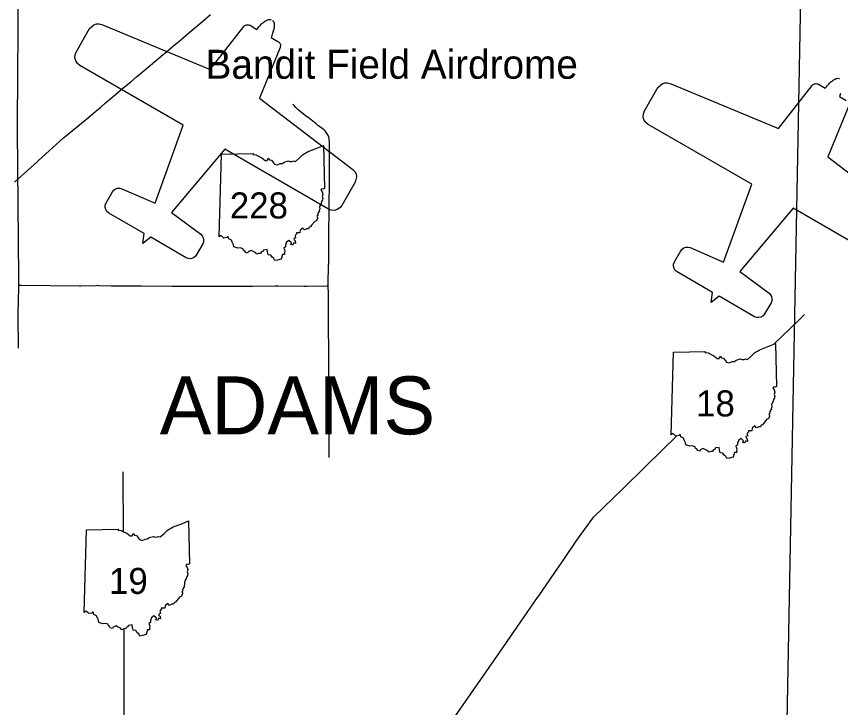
# Model space of a CAD drawing. Extents: x -232 to 448, y 619 to 1059.
# Drawn here: x 309.46 to 338.66, y 749.86 to 774.33 of the extents above; entities that cross this region are included whole.
import ezdxf

# ---------------------------------------------------------------- set-up
doc = ezdxf.new("R2010")
doc.units = 0
doc.layers.add('Default', color=7, linetype='Continuous')

msp = doc.modelspace()

# ---------------------------------------------------------------- linework, layer by layer
at = {"layer": 'Default'}
for p, q in [((316.641, 766.525), (316.723, 769.454)), ((316.641, 766.525), (316.723, 769.454)), ((332.657, 759.515), (332.739, 762.444)), ((332.657, 759.515), (332.739, 762.444)), ((311.857, 753.231), (311.939, 756.16)), ((311.857, 753.231), (311.939, 756.16))]:
    msp.add_line(p, q, dxfattribs=at)
for points in [[(336.743, 748.122), (337.363, 780.643)], [(309.543, 764.806), (309.541, 765.077), (309.503, 770.29), (309.502, 770.561), (309.535, 775.556), (309.534, 775.936), (309.528, 778.271), (309.527, 778.489)], [(309.392, 768.465), (310.198, 769.189), (310.243, 769.23), (311.128, 770.028), (311.187, 770.081), (311.899, 770.665), (311.899, 770.665), (311.954, 770.71), (312.106, 770.838), (312.272, 770.977), (312.447, 771.125), (312.62, 771.27), (312.815, 771.434), (313.052, 771.633), (313.291, 771.834), (313.514, 772.022), (313.713, 772.189), (313.92, 772.363), (314.126, 772.536), (314.366, 772.738), (314.587, 772.923), (314.789, 773.093), (315.035, 773.3), (315.284, 773.509), (315.571, 773.75), (315.853, 773.987), (316.067, 774.166), (316.343, 774.399)], [(313.936, 766.288), (313.987, 766.647), (312.734, 767.371), (312.67, 767.423), (312.626, 767.491), (312.604, 767.571), (312.609, 767.652), (312.638, 767.729), (312.865, 768.122), (312.912, 768.182), (312.975, 768.226), (313.047, 768.249), (313.123, 768.252), (313.196, 768.232), (314.376, 767.721), (315.375, 770.477), (311.706, 772.595), (311.621, 772.664), (311.561, 772.756), (311.533, 772.861), (311.539, 772.97), (311.578, 773.072), (312.056, 773.9), (312.199, 774.036), (312.294, 774.068), (312.395, 774.072), (312.492, 774.047), (316.329, 772.453), (317.515, 773.973), (317.535, 773.995), (317.556, 774.011), (317.575, 774.022), (317.598, 774.031), (317.626, 774.038), (317.657, 774.04), (317.689, 774.036), (317.714, 774.028), (317.74, 774.017), (317.985, 773.875), (318.002, 773.898), (318.028, 773.93), (318.055, 773.963), (318.084, 773.997), (318.11, 774.025), (318.137, 774.053), (318.162, 774.078), (318.185, 774.099), (318.208, 774.119), (318.235, 774.141), (318.26, 774.159), (318.295, 774.182), (318.33, 774.201), (318.363, 774.216), (318.398, 774.226), (318.429, 774.229), (318.46, 774.226), (318.485, 774.216)], [(318.528, 774.191), (318.549, 774.174), (318.568, 774.149), (318.58, 774.121), (318.589, 774.085), (318.593, 774.05), (318.594, 774.01), (318.591, 773.967), (318.588, 773.937), (318.582, 773.903), (318.576, 773.873), (318.57, 773.843), (318.561, 773.808), (318.55, 773.771), (318.539, 773.734), (318.524, 773.692), (318.509, 773.652), (318.494, 773.614), (318.483, 773.587), (318.728, 773.446), (318.751, 773.43), (318.77, 773.412), (318.789, 773.386), (318.803, 773.359), (318.812, 773.33), (318.815, 773.306), (318.815, 773.285), (318.811, 773.258), (318.803, 773.229), (318.079, 771.442), (321.379, 768.917), (321.449, 768.845), (321.496, 768.756), (321.515, 768.658), (321.469, 768.465), (320.991, 767.637), (320.922, 767.553), (320.831, 767.493), (320.725, 767.465), (320.616, 767.47), (320.514, 767.51), (316.844, 769.628), (314.957, 767.385), (315.99, 766.619), (316.044, 766.565), (316.08, 766.498), (316.095, 766.424), (316.089, 766.348), (316.061, 766.278), (315.833, 765.884), (315.782, 765.82), (315.713, 765.776), (315.634, 765.754), (315.552, 765.759), (315.476, 765.788), (314.222, 766.512), (313.936, 766.288)], [(334.072, 764.201), (334.124, 764.561), (332.87, 765.284), (332.806, 765.336), (332.762, 765.405), (332.741, 765.484), (332.745, 765.565), (332.774, 765.642), (333.002, 766.036), (333.049, 766.095), (333.111, 766.139), (333.183, 766.163), (333.259, 766.165), (333.332, 766.145), (334.513, 765.634), (335.512, 768.39), (331.842, 770.508), (331.757, 770.577), (331.697, 770.669), (331.669, 770.774), (331.675, 770.883), (331.714, 770.985), (332.192, 771.813), (332.336, 771.949), (332.431, 771.981), (332.531, 771.985), (332.628, 771.961), (336.465, 770.366), (337.651, 771.886), (337.671, 771.908), (337.693, 771.924), (337.712, 771.935), (337.734, 771.944), (337.763, 771.951), (337.793, 771.953), (337.825, 771.949), (337.851, 771.942), (337.876, 771.93), (338.121, 771.788), (338.139, 771.812), (338.164, 771.843), (338.191, 771.876), (338.22, 771.91), (338.246, 771.938), (338.273, 771.966), (338.299, 771.991), (338.321, 772.012), (338.345, 772.032), (338.372, 772.054), (338.396, 772.072), (338.432, 772.095), (338.466, 772.115), (338.499, 772.129), (338.534, 772.139), (338.565, 772.142), (338.596, 772.139), (338.622, 772.129)], [(338.661, 771.606), (338.646, 771.565), (338.631, 771.528), (338.619, 771.5), (338.864, 771.359)], [(320.509, 764.781), (320.51, 764.835), (320.524, 765.538), (320.525, 765.568), (320.526, 765.646), (320.533, 766.511), (320.533, 766.514), (320.534, 766.619), (320.537, 767.484), (320.537, 767.525), (320.538, 767.592), (320.55, 768.511), (320.55, 768.534), (320.55, 768.619), (320.554, 769.484), (320.554, 769.504), (320.553, 769.592), (320.55, 769.862), (320.55, 769.894), (320.54, 769.97), (320.526, 770.077), (320.525, 770.084), (320.472, 770.17), (320.415, 770.262), (320.4, 770.287), (320.336, 770.334), (320.162, 770.462), (320.145, 770.474), (320.077, 770.528), (319.781, 770.764), (319.775, 770.768), (319.695, 770.83), (319.438, 771.028), (319.416, 771.045), (319.363, 771.105), (319.291, 771.186), (319.255, 771.227)], [(338.939, 771.142), (338.216, 769.356), (341.515, 766.83)], [(316.723, 769.454), (317.86, 769.473), (317.842, 769.438), (317.949, 769.43), (318.063, 769.368), (318.159, 769.328), (318.277, 769.235), (318.348, 769.236), (318.378, 769.312), (318.432, 769.254), (318.496, 769.243), (318.606, 769.103), (318.698, 769.072), (318.807, 769.12), (318.889, 769.128), (318.949, 769.176), (319.105, 769.216), (319.149, 769.192), (319.231, 769.197), (319.273, 769.215), (319.345, 769.199), (319.471, 769.305), (319.602, 769.431), (319.803, 769.55), (320.102, 769.662), (320.339, 769.762), (320.374, 768.242)], [(316.723, 769.454), (317.86, 769.473), (317.842, 769.438), (317.949, 769.43), (318.063, 769.368), (318.159, 769.328), (318.277, 769.235), (318.348, 769.236), (318.378, 769.312), (318.432, 769.254), (318.496, 769.243), (318.606, 769.103), (318.698, 769.072), (318.807, 769.12), (318.889, 769.128), (318.949, 769.176), (319.105, 769.216), (319.149, 769.192), (319.231, 769.197), (319.273, 769.215), (319.345, 769.199), (319.471, 769.305), (319.602, 769.431), (319.803, 769.55), (320.102, 769.662), (320.339, 769.762), (320.374, 768.242)], [(320.374, 768.242), (320.339, 768.221), (320.284, 768.231), (320.248, 768.188), (320.293, 768.117), (320.314, 768.042), (320.295, 767.959), (320.314, 767.891), (320.301, 767.834), (320.267, 767.777), (320.255, 767.723), (320.226, 767.665), (320.229, 767.633), (320.201, 767.608), (320.206, 767.513), (320.192, 767.46), (320.197, 767.415), (320.152, 767.403), (320.162, 767.365), (320.133, 767.336), (320.14, 767.287), (320.107, 767.255), (320.139, 767.191), (320.113, 767.171), (320.092, 767.093), (320.035, 767.077), (319.919, 766.936), (319.878, 766.882), (319.832, 766.869), (319.807, 766.814), (319.751, 766.813), (319.665, 766.775), (319.61, 766.841), (319.514, 766.762), (319.502, 766.67), (319.38, 766.673), (319.385, 766.627), (319.358, 766.614), (319.333, 766.567), (319.347, 766.485), (319.29, 766.464), (319.297, 766.417), (319.334, 766.387), (319.35, 766.296), (319.289, 766.315), (319.239, 766.238), (319.188, 766.256), (319.205, 766.321), (319.118, 766.399), (319.036, 766.337), (318.994, 766.236), (318.993, 766.169), (318.932, 766.128), (318.971, 766.033), (318.964, 765.967), (318.965, 765.905), (318.889, 765.907), (318.843, 765.739)], [(320.374, 768.242), (320.339, 768.221), (320.284, 768.231), (320.248, 768.188), (320.293, 768.117), (320.314, 768.042), (320.295, 767.959), (320.314, 767.891), (320.301, 767.834), (320.267, 767.777), (320.255, 767.723), (320.226, 767.665), (320.229, 767.633), (320.201, 767.608), (320.206, 767.513), (320.192, 767.46), (320.197, 767.415), (320.152, 767.403), (320.162, 767.365), (320.133, 767.336), (320.14, 767.287), (320.107, 767.255), (320.139, 767.191), (320.113, 767.171), (320.092, 767.093), (320.035, 767.077), (319.919, 766.936), (319.878, 766.882), (319.832, 766.869), (319.807, 766.814), (319.751, 766.813), (319.665, 766.775), (319.61, 766.841), (319.514, 766.762), (319.502, 766.67), (319.38, 766.673), (319.385, 766.627), (319.358, 766.614), (319.333, 766.567), (319.347, 766.485), (319.29, 766.464), (319.297, 766.417), (319.334, 766.387), (319.35, 766.296), (319.289, 766.315), (319.239, 766.238), (319.188, 766.256), (319.205, 766.321), (319.118, 766.399), (319.036, 766.337), (318.994, 766.236), (318.993, 766.169), (318.932, 766.128), (318.971, 766.033), (318.964, 765.967), (318.965, 765.905), (318.889, 765.907), (318.843, 765.739)], [(340.651, 765.423), (336.981, 767.542), (335.094, 765.299), (336.126, 764.532), (336.18, 764.478), (336.216, 764.411), (336.232, 764.337), (336.225, 764.261), (336.197, 764.191), (335.97, 763.797), (335.918, 763.733), (335.849, 763.689), (335.77, 763.668), (335.689, 763.672), (335.612, 763.701), (334.359, 764.425), (334.072, 764.201)], [(318.843, 765.739), (318.71, 765.707), (318.618, 765.688), (318.586, 765.764), (318.52, 765.804), (318.477, 765.881), (318.382, 765.892), (318.36, 765.997), (318.349, 766.083), (318.22, 766.062), (318.185, 766.009), (318.139, 765.995), (318.112, 765.943), (318.05, 765.938), (317.983, 765.913), (317.939, 765.965), (317.829, 766.017), (317.78, 766.044), (317.676, 766.002), (317.654, 765.953), (317.572, 765.975), (317.553, 766.03), (317.503, 766.046), (317.492, 766.105), (317.386, 766.136), (317.304, 766.123), (317.161, 766.17), (317.152, 766.247), (317.103, 766.34), (317.078, 766.405), (316.987, 766.455), (316.969, 766.532), (316.94, 766.53), (316.913, 766.499), (316.812, 766.484), (316.772, 766.516), (316.716, 766.57), (316.641, 766.525)], [(318.843, 765.739), (318.71, 765.707), (318.618, 765.688), (318.586, 765.764), (318.52, 765.804), (318.477, 765.881), (318.382, 765.892), (318.36, 765.997), (318.349, 766.083), (318.22, 766.062), (318.185, 766.009), (318.139, 765.995), (318.112, 765.943), (318.05, 765.938), (317.983, 765.913), (317.939, 765.965), (317.829, 766.017), (317.78, 766.044), (317.676, 766.002), (317.654, 765.953), (317.572, 765.975), (317.553, 766.03), (317.503, 766.046), (317.492, 766.105), (317.386, 766.136), (317.304, 766.123), (317.161, 766.17), (317.152, 766.247), (317.103, 766.34), (317.078, 766.405), (316.987, 766.455), (316.969, 766.532), (316.94, 766.53), (316.913, 766.499), (316.812, 766.484), (316.772, 766.516), (316.716, 766.57), (316.641, 766.525)], [(309.538, 762.59), (309.52, 763.727), (309.519, 763.803), (309.541, 764.723), (309.541, 764.723), (309.543, 764.806)], [(320.509, 764.781), (320.455, 764.78), (319.756, 764.771), (319.741, 764.771), (319.648, 764.772), (318.735, 764.781), (318.712, 764.781), (318.627, 764.78), (317.821, 764.771), (317.779, 764.771), (316.752, 764.771), (316.692, 764.771), (315.455, 764.769), (315.405, 764.769), (315.348, 764.769), (315.079, 764.772), (315.029, 764.773), (314.971, 764.773), (313.896, 764.777), (313.887, 764.777), (313.789, 764.778), (312.929, 764.785), (312.883, 764.785), (312.821, 764.787), (312.391, 764.799), (312.376, 764.8), (312.283, 764.797), (311.746, 764.781), (311.691, 764.779), (309.633, 764.805), (309.633, 764.805), (309.543, 764.806)], [(320.531, 761.371), (320.519, 764.456), (320.518, 764.51), (320.516, 764.564), (320.511, 764.727), (320.509, 764.781)], [(336.296, 762.727), (337.156, 763.55), (337.21, 763.602), (337.384, 763.777)], [(332.739, 762.444), (333.876, 762.463), (333.858, 762.428), (333.965, 762.42), (334.079, 762.358), (334.175, 762.318), (334.293, 762.225), (334.364, 762.226), (334.394, 762.302), (334.448, 762.243), (334.512, 762.233), (334.622, 762.093), (334.714, 762.062), (334.823, 762.11), (334.905, 762.118), (334.965, 762.166), (335.121, 762.206), (335.165, 762.182), (335.247, 762.187), (335.289, 762.205), (335.361, 762.189), (335.487, 762.295), (335.618, 762.421), (335.819, 762.539), (336.118, 762.652), (336.355, 762.752), (336.39, 761.232)], [(332.739, 762.444), (333.876, 762.463), (333.858, 762.428), (333.965, 762.42), (334.079, 762.358), (334.175, 762.318), (334.293, 762.225), (334.364, 762.226), (334.394, 762.302), (334.448, 762.243), (334.512, 762.233), (334.622, 762.093), (334.714, 762.062), (334.823, 762.11), (334.905, 762.118), (334.965, 762.166), (335.121, 762.206), (335.165, 762.182), (335.247, 762.187), (335.289, 762.205), (335.361, 762.189), (335.487, 762.295), (335.618, 762.421), (335.819, 762.539), (336.118, 762.652), (336.355, 762.752), (336.39, 761.232)], [(320.54, 758.719), (320.531, 761.371)], [(336.39, 761.232), (336.355, 761.211), (336.3, 761.221), (336.264, 761.178), (336.309, 761.107), (336.33, 761.032), (336.311, 760.949), (336.33, 760.881), (336.317, 760.824), (336.283, 760.767), (336.271, 760.712), (336.242, 760.655), (336.245, 760.623), (336.217, 760.598), (336.222, 760.503), (336.208, 760.45), (336.213, 760.405), (336.168, 760.393), (336.178, 760.355), (336.149, 760.326), (336.156, 760.276), (336.123, 760.245), (336.155, 760.181), (336.129, 760.161), (336.108, 760.083), (336.051, 760.067), (335.935, 759.925), (335.894, 759.872), (335.848, 759.859), (335.823, 759.803), (335.767, 759.803), (335.681, 759.765), (335.626, 759.831), (335.53, 759.752), (335.518, 759.66), (335.396, 759.663), (335.401, 759.617), (335.374, 759.604), (335.349, 759.557), (335.363, 759.475), (335.306, 759.454), (335.313, 759.407), (335.35, 759.377), (335.366, 759.286), (335.305, 759.305), (335.255, 759.228), (335.204, 759.246), (335.221, 759.311), (335.134, 759.389), (335.052, 759.326), (335.01, 759.226), (335.009, 759.159), (334.948, 759.118), (334.987, 759.023), (334.98, 758.957), (334.981, 758.895), (334.905, 758.897), (334.859, 758.729)], [(336.39, 761.232), (336.355, 761.211), (336.3, 761.221), (336.264, 761.178), (336.309, 761.107), (336.33, 761.032), (336.311, 760.949), (336.33, 760.881), (336.317, 760.824), (336.283, 760.767), (336.271, 760.712), (336.242, 760.655), (336.245, 760.623), (336.217, 760.598), (336.222, 760.503), (336.208, 760.45), (336.213, 760.405), (336.168, 760.393), (336.178, 760.355), (336.149, 760.326), (336.156, 760.276), (336.123, 760.245), (336.155, 760.181), (336.129, 760.161), (336.108, 760.083), (336.051, 760.067), (335.935, 759.925), (335.894, 759.872), (335.848, 759.859), (335.823, 759.803), (335.767, 759.803), (335.681, 759.765), (335.626, 759.831), (335.53, 759.752), (335.518, 759.66), (335.396, 759.663), (335.401, 759.617), (335.374, 759.604), (335.349, 759.557), (335.363, 759.475), (335.306, 759.454), (335.313, 759.407), (335.35, 759.377), (335.366, 759.286), (335.305, 759.305), (335.255, 759.228), (335.204, 759.246), (335.221, 759.311), (335.134, 759.389), (335.052, 759.326), (335.01, 759.226), (335.009, 759.159), (334.948, 759.118), (334.987, 759.023), (334.98, 758.957), (334.981, 758.895), (334.905, 758.897), (334.859, 758.729)], [(324.914, 749.417), (325.749, 750.618), (325.808, 750.703), (326.798, 752.127), (326.85, 752.202), (327.927, 753.762), (327.967, 753.821), (328.8, 755.024), (328.831, 755.069), (329.317, 755.786), (329.373, 755.868), (329.883, 756.569), (329.92, 756.62), (330.935, 757.597), (331.005, 757.664), (331.702, 758.345), (331.702, 758.345), (331.765, 758.406), (332.856, 759.477)], [(334.859, 758.729), (334.726, 758.697), (334.634, 758.678), (334.602, 758.754), (334.536, 758.794), (334.493, 758.871), (334.398, 758.882), (334.376, 758.987), (334.365, 759.073), (334.236, 759.052), (334.201, 758.999), (334.155, 758.985), (334.128, 758.933), (334.066, 758.928), (333.999, 758.903), (333.955, 758.955), (333.845, 759.007), (333.796, 759.034), (333.692, 758.992), (333.67, 758.943), (333.588, 758.965), (333.569, 759.02), (333.519, 759.036), (333.508, 759.094), (333.402, 759.126), (333.32, 759.113), (333.177, 759.16), (333.168, 759.237), (333.119, 759.33), (333.094, 759.395), (333.003, 759.445), (332.985, 759.522), (332.956, 759.52), (332.929, 759.489), (332.829, 759.474), (332.788, 759.506), (332.732, 759.56), (332.657, 759.515)], [(334.859, 758.729), (334.726, 758.697), (334.634, 758.678), (334.602, 758.754), (334.536, 758.794), (334.493, 758.871), (334.398, 758.882), (334.376, 758.987), (334.365, 759.073), (334.236, 759.052), (334.201, 758.999), (334.155, 758.985), (334.128, 758.933), (334.066, 758.928), (333.999, 758.903), (333.955, 758.955), (333.845, 759.007), (333.796, 759.034), (333.692, 758.992), (333.67, 758.943), (333.588, 758.965), (333.569, 759.02), (333.519, 759.036), (333.508, 759.094), (333.402, 759.126), (333.32, 759.113), (333.177, 759.16), (333.168, 759.237), (333.119, 759.33), (333.094, 759.395), (333.003, 759.445), (332.985, 759.522), (332.956, 759.52), (332.929, 759.489), (332.829, 759.474), (332.788, 759.506), (332.732, 759.56), (332.657, 759.515)], [(313.254, 756.087), (313.239, 758.095), (313.239, 758.147), (313.239, 758.203)], [(311.939, 756.16), (313.075, 756.179), (313.057, 756.144), (313.164, 756.136), (313.278, 756.074), (313.375, 756.034), (313.493, 755.941), (313.563, 755.942), (313.593, 756.019), (313.647, 755.96), (313.711, 755.949), (313.822, 755.809), (313.913, 755.779), (314.023, 755.827), (314.105, 755.835), (314.164, 755.882), (314.32, 755.923), (314.364, 755.898), (314.446, 755.903), (314.488, 755.921), (314.56, 755.905), (314.687, 756.012), (314.817, 756.137), (315.018, 756.256), (315.318, 756.368), (315.555, 756.468), (315.589, 754.948)], [(311.939, 756.16), (313.075, 756.179), (313.057, 756.144), (313.164, 756.136), (313.278, 756.074), (313.375, 756.034), (313.493, 755.941), (313.563, 755.942), (313.593, 756.019), (313.647, 755.96), (313.711, 755.949), (313.822, 755.809), (313.913, 755.779), (314.023, 755.827), (314.105, 755.835), (314.164, 755.882), (314.32, 755.923), (314.364, 755.898), (314.446, 755.903), (314.488, 755.921), (314.56, 755.905), (314.687, 756.012), (314.817, 756.137), (315.018, 756.256), (315.318, 756.368), (315.555, 756.468), (315.589, 754.948)], [(315.589, 754.948), (315.554, 754.927), (315.499, 754.937), (315.463, 754.894), (315.508, 754.823), (315.53, 754.748), (315.511, 754.665), (315.529, 754.597), (315.517, 754.54), (315.482, 754.483), (315.471, 754.429), (315.441, 754.372), (315.444, 754.34), (315.416, 754.314), (315.421, 754.219), (315.407, 754.167), (315.412, 754.121), (315.367, 754.109), (315.377, 754.072), (315.349, 754.043), (315.355, 753.993), (315.322, 753.961), (315.354, 753.897), (315.329, 753.877), (315.308, 753.799), (315.25, 753.784), (315.134, 753.642), (315.093, 753.588), (315.048, 753.575), (315.022, 753.52), (314.966, 753.519), (314.881, 753.481), (314.825, 753.547), (314.729, 753.468), (314.718, 753.377), (314.595, 753.38), (314.6, 753.333), (314.573, 753.32), (314.548, 753.274), (314.562, 753.191), (314.505, 753.171), (314.512, 753.123), (314.549, 753.094), (314.565, 753.002), (314.504, 753.021), (314.454, 752.944), (314.403, 752.962), (314.42, 753.027), (314.333, 753.105), (314.252, 753.043), (314.209, 752.943), (314.208, 752.875), (314.147, 752.834), (314.186, 752.739), (314.179, 752.674), (314.18, 752.611), (314.104, 752.613), (314.058, 752.445)], [(315.589, 754.948), (315.554, 754.927), (315.499, 754.937), (315.463, 754.894), (315.508, 754.823), (315.53, 754.748), (315.511, 754.665), (315.529, 754.597), (315.517, 754.54), (315.482, 754.483), (315.471, 754.429), (315.441, 754.372), (315.444, 754.34), (315.416, 754.314), (315.421, 754.219), (315.407, 754.167), (315.412, 754.121), (315.367, 754.109), (315.377, 754.072), (315.349, 754.043), (315.355, 753.993), (315.322, 753.961), (315.354, 753.897), (315.329, 753.877), (315.308, 753.799), (315.25, 753.784), (315.134, 753.642), (315.093, 753.588), (315.048, 753.575), (315.022, 753.52), (314.966, 753.519), (314.881, 753.481), (314.825, 753.547), (314.729, 753.468), (314.718, 753.377), (314.595, 753.38), (314.6, 753.333), (314.573, 753.32), (314.548, 753.274), (314.562, 753.191), (314.505, 753.171), (314.512, 753.123), (314.549, 753.094), (314.565, 753.002), (314.504, 753.021), (314.454, 752.944), (314.403, 752.962), (314.42, 753.027), (314.333, 753.105), (314.252, 753.043), (314.209, 752.943), (314.208, 752.875), (314.147, 752.834), (314.186, 752.739), (314.179, 752.674), (314.18, 752.611), (314.104, 752.613), (314.058, 752.445)], [(314.058, 752.445), (313.925, 752.413), (313.833, 752.394), (313.801, 752.47), (313.735, 752.511), (313.692, 752.587), (313.598, 752.598), (313.575, 752.703), (313.565, 752.789), (313.435, 752.768), (313.4, 752.716), (313.354, 752.702), (313.327, 752.649), (313.265, 752.644), (313.198, 752.619), (313.154, 752.671), (313.044, 752.723), (312.995, 752.75), (312.892, 752.708), (312.869, 752.659), (312.787, 752.681), (312.768, 752.736), (312.718, 752.752), (312.707, 752.811), (312.601, 752.842), (312.52, 752.829), (312.376, 752.876), (312.367, 752.953), (312.319, 753.047), (312.293, 753.112), (312.202, 753.161), (312.184, 753.238), (312.155, 753.236), (312.128, 753.205), (312.028, 753.19), (311.988, 753.222), (311.931, 753.276), (311.857, 753.231)], [(314.058, 752.445), (313.925, 752.413), (313.833, 752.394), (313.801, 752.47), (313.735, 752.511), (313.692, 752.587), (313.598, 752.598), (313.575, 752.703), (313.565, 752.789), (313.435, 752.768), (313.4, 752.716), (313.354, 752.702), (313.327, 752.649), (313.265, 752.644), (313.198, 752.619), (313.154, 752.671), (313.044, 752.723), (312.995, 752.75), (312.892, 752.708), (312.869, 752.659), (312.787, 752.681), (312.768, 752.736), (312.718, 752.752), (312.707, 752.811), (312.601, 752.842), (312.52, 752.829), (312.376, 752.876), (312.367, 752.953), (312.319, 753.047), (312.293, 753.112), (312.202, 753.161), (312.184, 753.238), (312.155, 753.236), (312.128, 753.205), (312.028, 753.19), (311.988, 753.222), (311.931, 753.276), (311.857, 753.231)], [(313.016, 733.877), (313.055, 738.546), (313.055, 738.553), (313.056, 738.654), (313.078, 741.749), (313.078, 741.757), (313.078, 741.857), (313.076, 744.951), (313.076, 744.985), (313.076, 745.06), (313.077, 747.557), (313.077, 747.56), (313.082, 747.665), (313.091, 747.828), (313.094, 747.884), (313.105, 747.937), (313.271, 748.787), (313.28, 748.836), (313.28, 748.894), (313.277, 752.613)]]:
    msp.add_lwpolyline(points, dxfattribs=at)

# ---------------------------------------------------------------- texts
for s, height, p in [('Bandit Field Airdrome      ', 1.026, (316.163, 772.125)), ('228', 0.9234, (317.022, 767.178)), ('ADAMS', 2.052, (314.539, 759.534)), ('18', 0.9234, (333.543, 760.168)), ('19', 0.9234, (312.743, 753.884))]:
    msp.add_text(s, height=height, dxfattribs=at).set_placement(p)

doc.saveas('drawing.dxf')
